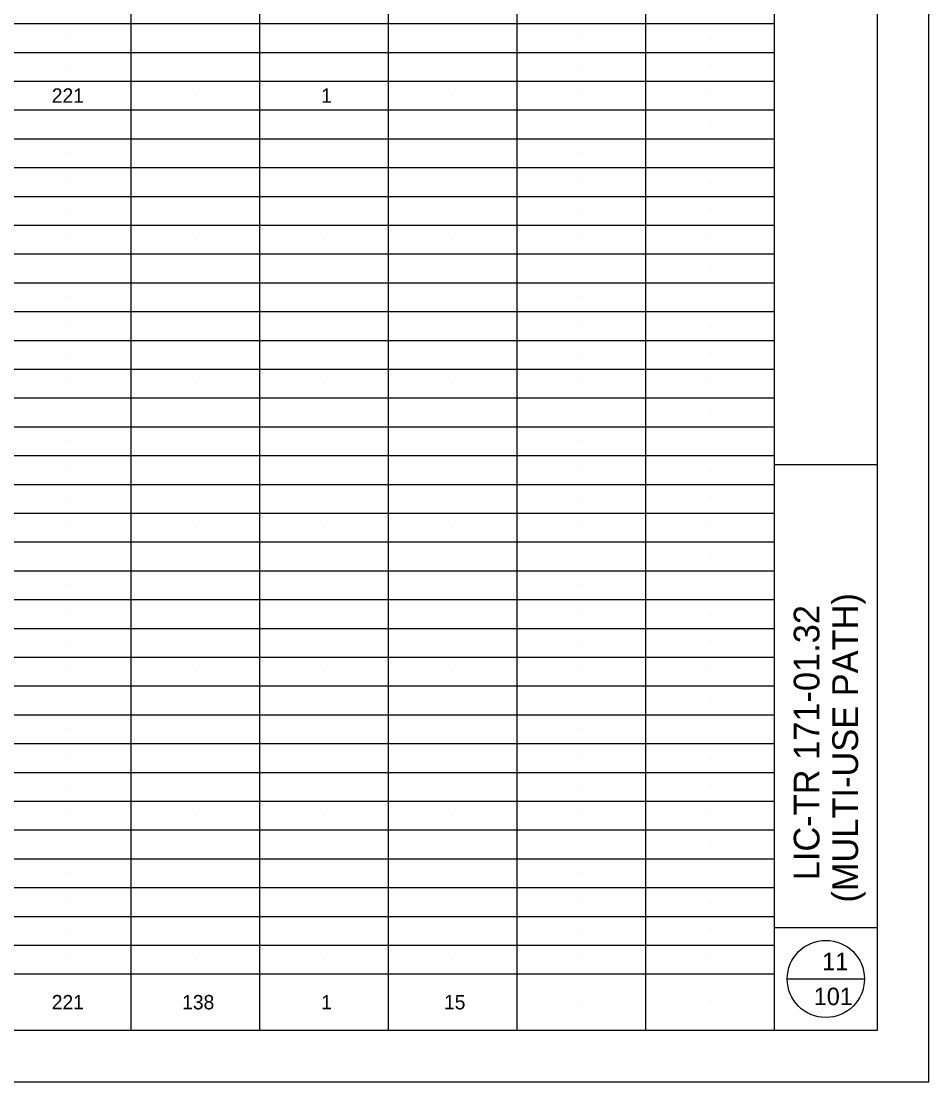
# Model space of a CAD drawing. Extents: x 2107022.8 to 2107056.8, y 706071 to 706093.
# Drawn here: x 2107047.99 to 2107056.81, y 706070.99 to 706081.3 of the extents above; entities that cross this region are included whole.
import ezdxf

# ---------------------------------------------------------------- set-up
doc = ezdxf.new("R2010")
doc.units = 0
for name, color, linetype in [('SC_Scratch1', 7, 'Continuous'), ('SH_Border', 7, 'Continuous'), ('SH_Cut_Line', 7, 'Continuous'), ('SH_Data', 7, 'Continuous'), ('SH_Text', 7, 'Continuous')]:
    doc.layers.add(name, color=color, linetype=linetype)

msp = doc.modelspace()

# ---------------------------------------------------------------- linework, layer by layer
at = {"layer": 'SC_Scratch1'}
for p, q in [((2107048.437, 706081.135), (2107048.437, 706081.135)), ((2107049.687, 706081.135), (2107049.687, 706081.135)), ((2107050.937, 706081.135), (2107050.937, 706081.135)), ((2107052.187, 706081.135), (2107052.187, 706081.135)), ((2107053.437, 706081.135), (2107053.437, 706081.135)), ((2107054.687, 706081.135), (2107054.687, 706081.135)), ((2107048.437, 706080.855), (2107048.437, 706080.855)), ((2107049.687, 706080.855), (2107049.687, 706080.855)), ((2107050.937, 706080.855), (2107050.937, 706080.855)), ((2107052.187, 706080.855), (2107052.187, 706080.855)), ((2107053.437, 706080.855), (2107053.437, 706080.855)), ((2107054.687, 706080.855), (2107054.687, 706080.855)), ((2107048.437, 706080.575), (2107048.437, 706080.575)), ((2107049.687, 706080.575), (2107049.687, 706080.575)), ((2107050.937, 706080.575), (2107050.937, 706080.575)), ((2107052.187, 706080.575), (2107052.187, 706080.575)), ((2107053.437, 706080.575), (2107053.437, 706080.575)), ((2107054.687, 706080.575), (2107054.687, 706080.575)), ((2107048.437, 706080.295), (2107048.437, 706080.295)), ((2107049.687, 706080.295), (2107049.687, 706080.295)), ((2107050.937, 706080.295), (2107050.937, 706080.295)), ((2107052.187, 706080.295), (2107052.187, 706080.295)), ((2107053.437, 706080.295), (2107053.437, 706080.295)), ((2107054.687, 706080.295), (2107054.687, 706080.295)), ((2107048.437, 706080.015), (2107048.437, 706080.015)), ((2107049.687, 706080.015), (2107049.687, 706080.015)), ((2107050.937, 706080.015), (2107050.937, 706080.015)), ((2107052.187, 706080.015), (2107052.187, 706080.015)), ((2107053.437, 706080.015), (2107053.437, 706080.015)), ((2107054.687, 706080.015), (2107054.687, 706080.015)), ((2107048.437, 706079.735), (2107048.437, 706079.735)), ((2107049.687, 706079.735), (2107049.687, 706079.735)), ((2107050.937, 706079.735), (2107050.937, 706079.735)), ((2107052.187, 706079.735), (2107052.187, 706079.735)), ((2107053.437, 706079.735), (2107053.437, 706079.735)), ((2107054.687, 706079.735), (2107054.687, 706079.735)), ((2107048.437, 706079.455), (2107048.437, 706079.455)), ((2107049.687, 706079.455), (2107049.687, 706079.455)), ((2107050.937, 706079.455), (2107050.937, 706079.455)), ((2107052.187, 706079.455), (2107052.187, 706079.455)), ((2107053.437, 706079.455), (2107053.437, 706079.455)), ((2107054.687, 706079.455), (2107054.687, 706079.455)), ((2107048.437, 706079.175), (2107048.437, 706079.175)), ((2107049.687, 706079.175), (2107049.687, 706079.175)), ((2107050.937, 706079.175), (2107050.937, 706079.175)), ((2107052.187, 706079.175), (2107052.187, 706079.175)), ((2107053.437, 706079.175), (2107053.437, 706079.175)), ((2107054.687, 706079.175), (2107054.687, 706079.175)), ((2107048.437, 706078.895), (2107048.437, 706078.895)), ((2107049.687, 706078.895), (2107049.687, 706078.895)), ((2107050.937, 706078.895), (2107050.937, 706078.895)), ((2107052.187, 706078.895), (2107052.187, 706078.895)), ((2107053.437, 706078.895), (2107053.437, 706078.895)), ((2107054.687, 706078.895), (2107054.687, 706078.895)), ((2107048.437, 706078.615), (2107048.437, 706078.615)), ((2107049.687, 706078.615), (2107049.687, 706078.615)), ((2107050.937, 706078.615), (2107050.937, 706078.615)), ((2107052.187, 706078.615), (2107052.187, 706078.615)), ((2107053.437, 706078.615), (2107053.437, 706078.615)), ((2107054.687, 706078.615), (2107054.687, 706078.615)), ((2107048.437, 706078.335), (2107048.437, 706078.335)), ((2107049.687, 706078.335), (2107049.687, 706078.335)), ((2107050.937, 706078.335), (2107050.937, 706078.335)), ((2107052.187, 706078.335), (2107052.187, 706078.335)), ((2107053.437, 706078.335), (2107053.437, 706078.335)), ((2107054.687, 706078.335), (2107054.687, 706078.335)), ((2107048.437, 706078.055), (2107048.437, 706078.055)), ((2107049.687, 706078.055), (2107049.687, 706078.055)), ((2107050.937, 706078.055), (2107050.937, 706078.055)), ((2107052.187, 706078.055), (2107052.187, 706078.055)), ((2107053.437, 706078.055), (2107053.437, 706078.055)), ((2107054.687, 706078.055), (2107054.687, 706078.055)), ((2107048.437, 706077.775), (2107048.437, 706077.775)), ((2107049.687, 706077.775), (2107049.687, 706077.775)), ((2107050.937, 706077.775), (2107050.937, 706077.775)), ((2107052.187, 706077.775), (2107052.187, 706077.775)), ((2107053.437, 706077.775), (2107053.437, 706077.775)), ((2107054.687, 706077.775), (2107054.687, 706077.775)), ((2107048.437, 706077.495), (2107048.437, 706077.495)), ((2107049.687, 706077.495), (2107049.687, 706077.495)), ((2107050.937, 706077.495), (2107050.937, 706077.495)), ((2107052.187, 706077.495), (2107052.187, 706077.495)), ((2107053.437, 706077.495), (2107053.437, 706077.495)), ((2107054.687, 706077.495), (2107054.687, 706077.495)), ((2107048.437, 706077.215), (2107048.437, 706077.215)), ((2107049.687, 706077.215), (2107049.687, 706077.215)), ((2107050.937, 706077.215), (2107050.937, 706077.215)), ((2107052.187, 706077.215), (2107052.187, 706077.215)), ((2107053.437, 706077.215), (2107053.437, 706077.215)), ((2107054.687, 706077.215), (2107054.687, 706077.215)), ((2107048.437, 706076.935), (2107048.437, 706076.935)), ((2107048.437, 706076.935), (2107048.437, 706076.935)), ((2107049.687, 706076.935), (2107049.687, 706076.935)), ((2107049.687, 706076.935), (2107049.687, 706076.935)), ((2107050.937, 706076.935), (2107050.937, 706076.935)), ((2107050.937, 706076.935), (2107050.937, 706076.935)), ((2107052.187, 706076.935), (2107052.187, 706076.935)), ((2107052.187, 706076.935), (2107052.187, 706076.935)), ((2107053.437, 706076.935), (2107053.437, 706076.935)), ((2107053.437, 706076.935), (2107053.437, 706076.935)), ((2107054.687, 706076.935), (2107054.687, 706076.935)), ((2107054.687, 706076.935), (2107054.687, 706076.935)), ((2107048.437, 706076.655), (2107048.437, 706076.655)), ((2107049.687, 706076.655), (2107049.687, 706076.655)), ((2107050.937, 706076.655), (2107050.937, 706076.655)), ((2107052.187, 706076.655), (2107052.187, 706076.655)), ((2107053.437, 706076.655), (2107053.437, 706076.655)), ((2107054.687, 706076.655), (2107054.687, 706076.655)), ((2107048.437, 706076.375), (2107048.437, 706076.375)), ((2107049.687, 706076.375), (2107049.687, 706076.375)), ((2107050.937, 706076.375), (2107050.937, 706076.375)), ((2107052.187, 706076.375), (2107052.187, 706076.375)), ((2107053.437, 706076.375), (2107053.437, 706076.375)), ((2107054.687, 706076.375), (2107054.687, 706076.375)), ((2107048.437, 706076.095), (2107048.437, 706076.095)), ((2107049.687, 706076.095), (2107049.687, 706076.095)), ((2107050.937, 706076.095), (2107050.937, 706076.095)), ((2107052.187, 706076.095), (2107052.187, 706076.095)), ((2107053.437, 706076.095), (2107053.437, 706076.095)), ((2107054.687, 706076.095), (2107054.687, 706076.095)), ((2107048.437, 706075.815), (2107048.437, 706075.815)), ((2107049.687, 706075.815), (2107049.687, 706075.815)), ((2107050.937, 706075.815), (2107050.937, 706075.815)), ((2107052.187, 706075.815), (2107052.187, 706075.815)), ((2107053.437, 706075.815), (2107053.437, 706075.815)), ((2107054.687, 706075.815), (2107054.687, 706075.815)), ((2107048.437, 706075.535), (2107048.437, 706075.535)), ((2107049.687, 706075.535), (2107049.687, 706075.535)), ((2107050.937, 706075.535), (2107050.937, 706075.535)), ((2107052.187, 706075.535), (2107052.187, 706075.535)), ((2107053.437, 706075.535), (2107053.437, 706075.535)), ((2107054.687, 706075.535), (2107054.687, 706075.535)), ((2107048.437, 706075.255), (2107048.437, 706075.255)), ((2107049.687, 706075.255), (2107049.687, 706075.255)), ((2107050.937, 706075.255), (2107050.937, 706075.255)), ((2107052.187, 706075.255), (2107052.187, 706075.255)), ((2107053.437, 706075.255), (2107053.437, 706075.255)), ((2107054.687, 706075.255), (2107054.687, 706075.255)), ((2107048.437, 706074.975), (2107048.437, 706074.975)), ((2107048.437, 706074.975), (2107048.437, 706074.975)), ((2107049.687, 706074.975), (2107049.687, 706074.975)), ((2107049.687, 706074.975), (2107049.687, 706074.975)), ((2107050.937, 706074.975), (2107050.937, 706074.975)), ((2107050.937, 706074.975), (2107050.937, 706074.975)), ((2107052.187, 706074.975), (2107052.187, 706074.975)), ((2107052.187, 706074.975), (2107052.187, 706074.975)), ((2107053.437, 706074.975), (2107053.437, 706074.975)), ((2107053.437, 706074.975), (2107053.437, 706074.975)), ((2107054.687, 706074.975), (2107054.687, 706074.975)), ((2107054.687, 706074.975), (2107054.687, 706074.975)), ((2107048.437, 706074.695), (2107048.437, 706074.695)), ((2107049.687, 706074.695), (2107049.687, 706074.695)), ((2107050.937, 706074.695), (2107050.937, 706074.695)), ((2107052.187, 706074.695), (2107052.187, 706074.695)), ((2107053.437, 706074.695), (2107053.437, 706074.695)), ((2107054.687, 706074.695), (2107054.687, 706074.695)), ((2107048.437, 706074.415), (2107048.437, 706074.415)), ((2107049.687, 706074.415), (2107049.687, 706074.415)), ((2107050.937, 706074.415), (2107050.937, 706074.415)), ((2107052.187, 706074.415), (2107052.187, 706074.415)), ((2107053.437, 706074.415), (2107053.437, 706074.415)), ((2107054.687, 706074.415), (2107054.687, 706074.415)), ((2107048.437, 706074.135), (2107048.437, 706074.135)), ((2107049.687, 706074.135), (2107049.687, 706074.135)), ((2107050.937, 706074.135), (2107050.937, 706074.135)), ((2107052.187, 706074.135), (2107052.187, 706074.135)), ((2107053.437, 706074.135), (2107053.437, 706074.135)), ((2107054.687, 706074.135), (2107054.687, 706074.135)), ((2107048.437, 706073.855), (2107048.437, 706073.855)), ((2107048.437, 706073.855), (2107048.437, 706073.855)), ((2107049.687, 706073.855), (2107049.687, 706073.855)), ((2107049.687, 706073.855), (2107049.687, 706073.855)), ((2107050.937, 706073.855), (2107050.937, 706073.855)), ((2107050.937, 706073.855), (2107050.937, 706073.855)), ((2107052.187, 706073.855), (2107052.187, 706073.855)), ((2107052.187, 706073.855), (2107052.187, 706073.855)), ((2107053.437, 706073.855), (2107053.437, 706073.855)), ((2107053.437, 706073.855), (2107053.437, 706073.855)), ((2107054.687, 706073.855), (2107054.687, 706073.855)), ((2107054.687, 706073.855), (2107054.687, 706073.855)), ((2107048.437, 706073.575), (2107048.437, 706073.575)), ((2107048.437, 706073.575), (2107048.437, 706073.575)), ((2107049.687, 706073.575), (2107049.687, 706073.575)), ((2107049.687, 706073.575), (2107049.687, 706073.575)), ((2107050.937, 706073.575), (2107050.937, 706073.575)), ((2107050.937, 706073.575), (2107050.937, 706073.575)), ((2107052.187, 706073.575), (2107052.187, 706073.575)), ((2107052.187, 706073.575), (2107052.187, 706073.575)), ((2107053.437, 706073.575), (2107053.437, 706073.575)), ((2107053.437, 706073.575), (2107053.437, 706073.575)), ((2107054.687, 706073.575), (2107054.687, 706073.575)), ((2107054.687, 706073.575), (2107054.687, 706073.575)), ((2107048.437, 706073.295), (2107048.437, 706073.295)), ((2107048.437, 706073.295), (2107048.437, 706073.295)), ((2107049.687, 706073.295), (2107049.687, 706073.295)), ((2107049.687, 706073.295), (2107049.687, 706073.295)), ((2107050.937, 706073.295), (2107050.937, 706073.295)), ((2107050.937, 706073.295), (2107050.937, 706073.295)), ((2107052.187, 706073.295), (2107052.187, 706073.295)), ((2107052.187, 706073.295), (2107052.187, 706073.295)), ((2107053.437, 706073.295), (2107053.437, 706073.295)), ((2107053.437, 706073.295), (2107053.437, 706073.295)), ((2107054.687, 706073.295), (2107054.687, 706073.295)), ((2107054.687, 706073.295), (2107054.687, 706073.295)), ((2107048.437, 706073.015), (2107048.437, 706073.015)), ((2107048.437, 706073.015), (2107048.437, 706073.015)), ((2107049.687, 706073.015), (2107049.687, 706073.015)), ((2107049.687, 706073.015), (2107049.687, 706073.015)), ((2107050.937, 706073.015), (2107050.937, 706073.015)), ((2107050.937, 706073.015), (2107050.937, 706073.015)), ((2107052.187, 706073.015), (2107052.187, 706073.015)), ((2107052.187, 706073.015), (2107052.187, 706073.015)), ((2107053.437, 706073.015), (2107053.437, 706073.015)), ((2107053.437, 706073.015), (2107053.437, 706073.015)), ((2107054.687, 706073.015), (2107054.687, 706073.015)), ((2107054.687, 706073.015), (2107054.687, 706073.015)), ((2107048.437, 706072.735), (2107048.437, 706072.735)), ((2107048.437, 706072.735), (2107048.437, 706072.735)), ((2107049.687, 706072.735), (2107049.687, 706072.735)), ((2107049.687, 706072.735), (2107049.687, 706072.735)), ((2107050.937, 706072.735), (2107050.937, 706072.735)), ((2107050.937, 706072.735), (2107050.937, 706072.735)), ((2107052.187, 706072.735), (2107052.187, 706072.735)), ((2107052.187, 706072.735), (2107052.187, 706072.735)), ((2107053.437, 706072.735), (2107053.437, 706072.735)), ((2107053.437, 706072.735), (2107053.437, 706072.735)), ((2107054.687, 706072.735), (2107054.687, 706072.735)), ((2107054.687, 706072.735), (2107054.687, 706072.735)), ((2107048.437, 706072.455), (2107048.437, 706072.455)), ((2107048.437, 706072.455), (2107048.437, 706072.455)), ((2107049.687, 706072.455), (2107049.687, 706072.455)), ((2107049.687, 706072.455), (2107049.687, 706072.455)), ((2107050.937, 706072.455), (2107050.937, 706072.455)), ((2107050.937, 706072.455), (2107050.937, 706072.455)), ((2107052.187, 706072.455), (2107052.187, 706072.455)), ((2107052.187, 706072.455), (2107052.187, 706072.455)), ((2107053.437, 706072.455), (2107053.437, 706072.455)), ((2107053.437, 706072.455), (2107053.437, 706072.455)), ((2107054.687, 706072.455), (2107054.687, 706072.455)), ((2107054.687, 706072.455), (2107054.687, 706072.455)), ((2107048.437, 706072.175), (2107048.437, 706072.175)), ((2107048.437, 706072.175), (2107048.437, 706072.175)), ((2107049.687, 706072.175), (2107049.687, 706072.175)), ((2107049.687, 706072.175), (2107049.687, 706072.175)), ((2107050.937, 706072.175), (2107050.937, 706072.175)), ((2107050.937, 706072.175), (2107050.937, 706072.175)), ((2107052.187, 706072.175), (2107052.187, 706072.175)), ((2107052.187, 706072.175), (2107052.187, 706072.175)), ((2107053.437, 706072.175), (2107053.437, 706072.175)), ((2107053.437, 706072.175), (2107053.437, 706072.175)), ((2107054.687, 706072.175), (2107054.687, 706072.175)), ((2107054.687, 706072.175), (2107054.687, 706072.175)), ((2107048.437, 706071.761), (2107048.437, 706071.761)), ((2107049.687, 706071.761), (2107049.687, 706071.761)), ((2107050.937, 706071.761), (2107050.937, 706071.761)), ((2107052.187, 706071.761), (2107052.187, 706071.761)), ((2107053.437, 706071.761), (2107053.437, 706071.761)), ((2107054.687, 706071.761), (2107054.687, 706071.761))]:
    msp.add_line(p, q, dxfattribs=at)
at = {"layer": 'SH_Border'}
for p, q in [((2107055.312, 706071.487), (2107055.312, 706092.487)), ((2107055.312, 706071.487), (2107055.312, 706092.487)), ((2107055.312, 706076.987), (2107056.312, 706076.987)), ((2107055.312, 706072.487), (2107056.312, 706072.487))]:
    msp.add_line(p, q, dxfattribs=at)
msp.add_lwpolyline([(2107024.812, 706092.487), (2107056.312, 706092.487), (2107056.312, 706071.487), (2107024.812, 706071.487)], close=True, dxfattribs=at)
at = {"layer": 'SH_Cut_Line'}
msp.add_lwpolyline([(2107022.812, 706070.987), (2107056.812, 706070.987), (2107056.812, 706092.987), (2107022.812, 706092.987)], close=True, dxfattribs=at)
at = {"layer": 'SH_Data'}
for p, q in [((2107049.062, 706071.487), (2107049.062, 706092.487)), ((2107050.312, 706071.487), (2107050.312, 706092.487)), ((2107051.562, 706071.487), (2107051.562, 706092.487)), ((2107052.812, 706071.487), (2107052.812, 706092.487)), ((2107054.062, 706071.487), (2107054.062, 706092.487)), ((2107024.812, 706081.275), (2107055.312, 706081.275)), ((2107024.812, 706080.995), (2107055.312, 706080.995)), ((2107024.812, 706080.715), (2107055.312, 706080.715)), ((2107024.812, 706080.435), (2107055.312, 706080.435)), ((2107024.812, 706080.155), (2107055.312, 706080.155)), ((2107024.812, 706079.875), (2107055.312, 706079.875)), ((2107024.812, 706079.595), (2107055.312, 706079.595)), ((2107024.812, 706079.315), (2107055.312, 706079.315)), ((2107024.812, 706079.035), (2107055.312, 706079.035)), ((2107024.812, 706078.755), (2107055.312, 706078.755)), ((2107024.812, 706078.475), (2107055.312, 706078.475)), ((2107024.812, 706078.195), (2107055.312, 706078.195)), ((2107024.812, 706077.915), (2107055.312, 706077.915)), ((2107024.812, 706077.635), (2107055.312, 706077.635)), ((2107024.812, 706077.355), (2107055.312, 706077.355)), ((2107024.812, 706077.075), (2107055.312, 706077.075)), ((2107024.812, 706076.795), (2107055.312, 706076.795)), ((2107024.812, 706076.515), (2107055.312, 706076.515)), ((2107024.812, 706076.235), (2107055.312, 706076.235)), ((2107024.812, 706075.955), (2107055.312, 706075.955)), ((2107024.812, 706075.675), (2107055.312, 706075.675)), ((2107024.812, 706075.395), (2107055.312, 706075.395)), ((2107024.812, 706075.115), (2107055.312, 706075.115)), ((2107024.812, 706074.835), (2107055.312, 706074.835)), ((2107024.812, 706074.555), (2107055.312, 706074.555)), ((2107024.812, 706074.275), (2107055.312, 706074.275)), ((2107024.812, 706073.995), (2107055.312, 706073.995)), ((2107024.812, 706073.715), (2107055.312, 706073.715)), ((2107024.812, 706073.435), (2107055.312, 706073.435)), ((2107024.812, 706073.155), (2107055.312, 706073.155)), ((2107024.812, 706072.875), (2107055.312, 706072.875)), ((2107024.812, 706072.595), (2107055.312, 706072.595)), ((2107024.812, 706072.315), (2107055.312, 706072.315)), ((2107024.812, 706072.035), (2107055.312, 706072.035)), ((2107055.437, 706071.987), (2107056.187, 706071.987))]:
    msp.add_line(p, q, dxfattribs=at)
msp.add_circle((2107055.812, 706071.987), 0.375, dxfattribs=at)

# ---------------------------------------------------------------- texts
for s, p in [('(MULTI-USE PATH)', (2107056.125, 706072.729)), ('LIC-TR 171-01.32', (2107055.75, 706072.946))]:
    msp.add_text(s, height=0.25, rotation=90, dxfattribs=at).set_placement(p)
for s, p in [('11', (2107055.777, 706072.072)), ('101', (2107055.695, 706071.732))]:
    msp.add_text(s, height=0.17, dxfattribs=at).set_placement(p)
at = {"layer": 'SH_Text'}
for s, p in [('221', (2107048.289, 706080.505)), ('1', (2107050.908, 706080.505)), ('221', (2107048.289, 706071.691)), ('138', (2107049.556, 706071.691)), ('1', (2107050.908, 706071.691)), ('15', (2107052.101, 706071.691))]:
    msp.add_text(s, height=0.14, dxfattribs=at).set_placement(p)

doc.saveas('drawing.dxf')
